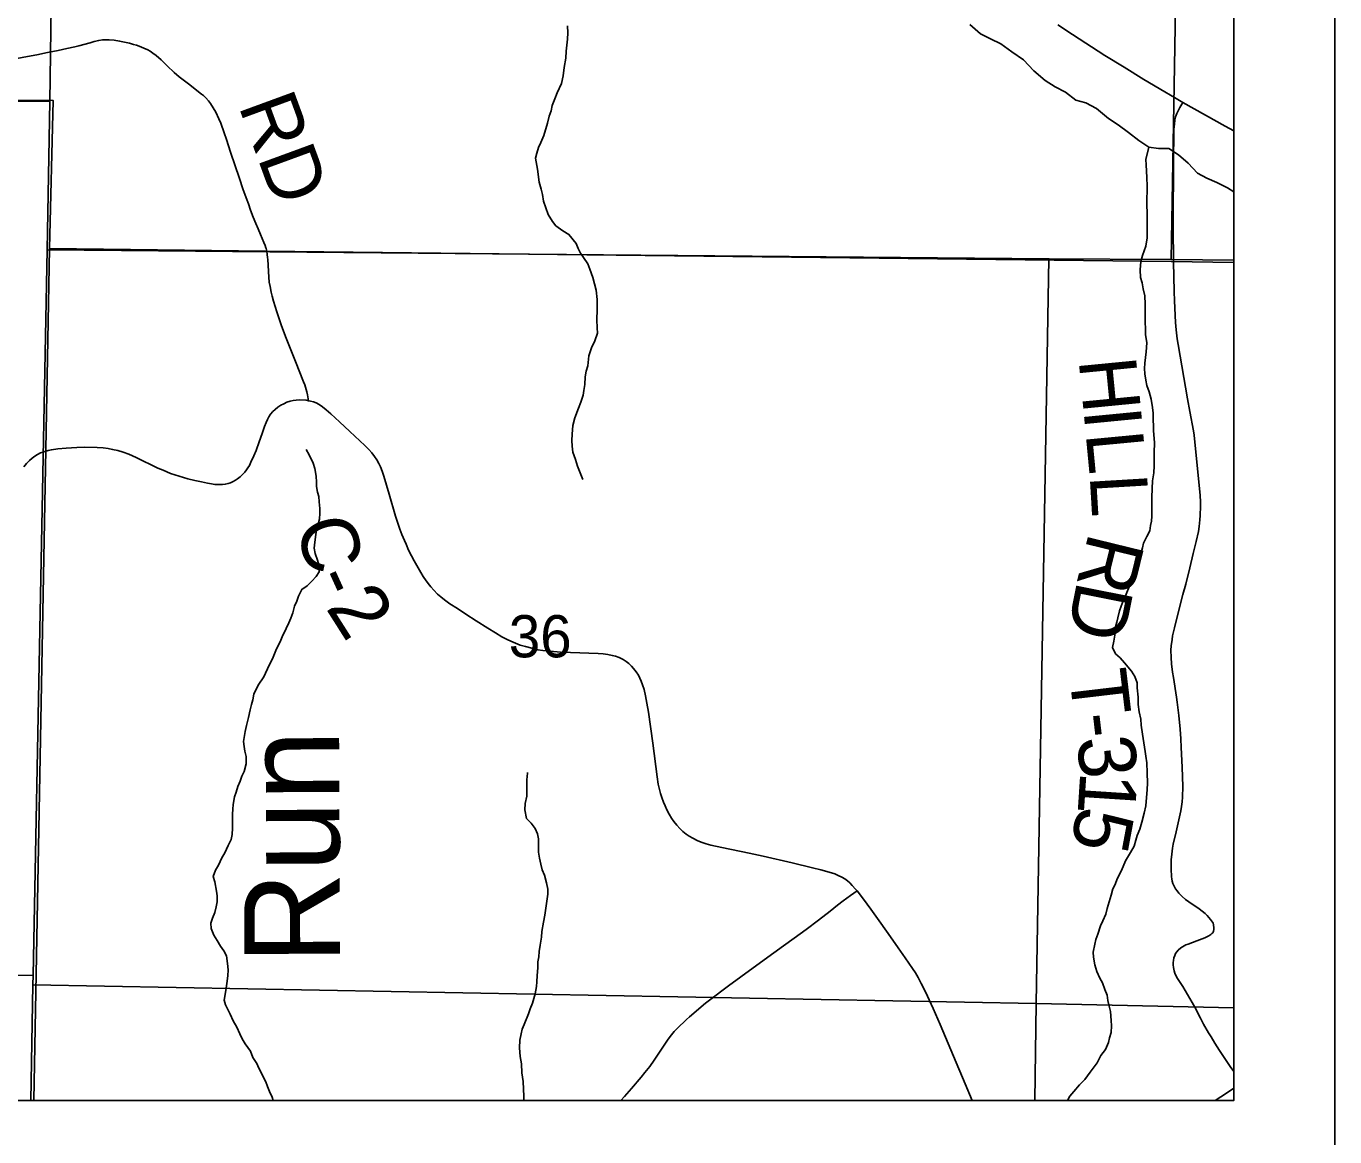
# Model space of a CAD drawing. Extents: x 0 to 34, y 0 to 22.
# Drawn here: x 24.203 to 25.5, y 13.564 to 14.665 of the extents above; entities that cross this region are included whole.
import ezdxf

# ---------------------------------------------------------------- set-up
doc = ezdxf.new("R2010")
doc.units = 0
for name, color, linetype in [('GM_X_Corporation', 7, 'Continuous'), ('GM_X_County_Road', 7, 'Continuous'), ('GM_X_County_Road_Text', 7, 'Continuous'), ('GM_X_Major_River', 7, 'Continuous'), ('GM_X_Minor_River', 7, 'Continuous'), ('GM_X_Minor_River_Text', 7, 'Continuous'), ('GM_X_Section_Text', 7, 'Continuous'), ('GM_X_Township_Road', 7, 'Continuous'), ('GM_X_Township_Road_Text', 7, 'Continuous'), ('GM_X_US_Route', 7, 'Continuous'), ('SH_Data', 7, 'Continuous')]:
    doc.layers.add(name, color=color, linetype=linetype)

msp = doc.modelspace()

# ---------------------------------------------------------------- linework, layer by layer
at = {"layer": 'GM_X_Corporation'}
msp.add_lwpolyline([(20.2208, 16.9558), (20.1987, 15.2691), (20.203, 14.81), (20.2016, 14.6512), (20.2571, 14.6508), (21.1282, 14.6279), (21.314, 14.623), (22.3464, 14.612), (22.9003, 14.6033), (24.2301, 14.5912), (24.2265, 14.4444), (24.4406, 14.442), (25.338, 14.4317), (25.4, 14.4307), (25.4, 19.0068)], dxfattribs=at)
for points in [[(23.2418, 15.623), (24.2407, 15.6067), (24.2392, 15.4615), (24.2269, 14.5903), (23.2254, 14.5998)], [(24.2392, 15.4615), (25.3552, 15.4512), (25.338, 14.4337), (25.2167, 14.4344), (24.2243, 14.4432), (24.2269, 14.5903)], [(25.4, 14.4329), (25.4, 15.4506), (25.3552, 15.4512), (25.338, 14.4337)], [(18.6, 14.6606), (18.6, 13.6), (24.2109, 13.6), (24.2228, 14.2453), (24.2265, 14.4444), (24.2301, 14.5912), (22.9003, 14.6033), (22.3464, 14.612), (21.314, 14.623), (21.1282, 14.6279), (20.2571, 14.6508), (20.2016, 14.6512), (19.8855, 14.6528), (19.4007, 14.6554), (18.9216, 14.6592)], [(23.2254, 14.5998), (24.2269, 14.5903), (24.2243, 14.4432), (24.2104, 13.724), (23.2038, 13.7171)], [(24.2109, 13.6), (25.4, 13.6), (25.4, 14.4307), (25.338, 14.4317), (24.4406, 14.442), (24.2265, 14.4444), (24.2228, 14.2453)], [(24.2243, 14.4432), (25.2167, 14.4344), (25.2042, 13.6962), (24.2101, 13.7145), (24.2104, 13.724)], [(25.4, 13.6919), (25.4, 14.4329), (25.338, 14.4337), (25.2167, 14.4344), (25.2042, 13.6962)], [(23.201, 13.6), (24.208, 13.6), (24.2101, 13.7145), (24.2104, 13.724), (23.2038, 13.7171)], [(24.208, 13.6), (25.2027, 13.6), (25.2042, 13.6962), (24.2101, 13.7145)], [(25.2027, 13.6), (25.4, 13.6), (25.4, 13.6919), (25.2042, 13.6962)]]:
    msp.add_lwpolyline(points, close=True, dxfattribs=at)
at = {"layer": 'GM_X_County_Road'}
for points in [[(24.2198, 14.2427), (24.2218, 14.2434), (24.2252, 14.2443), (24.2285, 14.245), (24.2349, 14.2459), (24.2429, 14.2467), (24.2536, 14.2473), (24.2611, 14.2475), (24.2737, 14.2473), (24.2798, 14.2468), (24.2848, 14.2461), (24.2891, 14.2453), (24.2943, 14.2441), (24.2994, 14.2426), (24.3051, 14.2405), (24.3124, 14.2372), (24.334, 14.2269), (24.339, 14.2246), (24.3465, 14.2216), (24.3507, 14.2201), (24.3637, 14.2163), (24.3704, 14.2146), (24.3772, 14.2131), (24.3832, 14.2119), (24.3872, 14.2112), (24.3904, 14.2107), (24.393, 14.2105), (24.3953, 14.2104), (24.398, 14.2105), (24.4007, 14.2108), (24.4034, 14.2114), (24.4057, 14.2122), (24.4084, 14.2135), (24.4107, 14.2147), (24.4129, 14.2162), (24.4153, 14.2181), (24.4178, 14.2203), (24.4201, 14.2228), (24.4218, 14.2252), (24.4232, 14.2271), (24.4246, 14.2295), (24.4261, 14.2326), (24.429, 14.2389), (24.4313, 14.2441), (24.4344, 14.253), (24.4372, 14.261), (24.4397, 14.2682), (24.4412, 14.2721), (24.4426, 14.2751), (24.444, 14.2776), (24.4456, 14.2801), (24.4477, 14.2828), (24.4502, 14.2849), (24.4528, 14.2871), (24.4557, 14.2891), (24.4586, 14.2906), (24.4618, 14.292), (24.4649, 14.2932), (24.4678, 14.2938), (24.471, 14.2942), (24.4747, 14.2944), (24.4808, 14.294), (24.483, 14.2936), (24.4851, 14.2932), (24.488, 14.2924), (24.4906, 14.2914), (24.4936, 14.2898), (24.497, 14.2876), (24.5008, 14.2847), (24.5054, 14.2806), (24.5139, 14.2726), (24.5242, 14.2631), (24.5389, 14.2491), (24.5428, 14.2452), (24.546, 14.2418), (24.5485, 14.2384), (24.5508, 14.2351), (24.5527, 14.2315), (24.5544, 14.228), (24.5561, 14.2238), (24.5578, 14.2189), (24.5632, 14.2011), (24.5695, 14.1791), (24.5724, 14.1702), (24.5738, 14.1662), (24.5757, 14.161), (24.5781, 14.1551), (24.5798, 14.1513), (24.5823, 14.1456), (24.5851, 14.1399), (24.5879, 14.1349), (24.5917, 14.1279), (24.5946, 14.1232), (24.5969, 14.1195), (24.5998, 14.1151), (24.603, 14.1109), (24.6043, 14.1092), (24.6073, 14.1058), (24.6109, 14.102), (24.6141, 14.0991), (24.6179, 14.0961), (24.6233, 14.0923), (24.6307, 14.0875), (24.639, 14.0821), (24.6494, 14.0753), (24.6607, 14.0682), (24.6684, 14.0634), (24.6748, 14.0597), (24.68, 14.0569), (24.6837, 14.0551), (24.6881, 14.0532), (24.6929, 14.0514), (24.6981, 14.0498), (24.7043, 14.0482), (24.7105, 14.0468), (24.7154, 14.046), (24.7188, 14.0455), (24.7225, 14.0452), (24.7329, 14.0445), (24.7427, 14.0441), (24.7701, 14.043), (24.7751, 14.0426), (24.7798, 14.042), (24.7841, 14.0412), (24.7874, 14.0404), (24.791, 14.039), (24.7948, 14.0372), (24.7978, 14.0352), (24.8006, 14.033), (24.8032, 14.0304), (24.8053, 14.0281), (24.8078, 14.0249), (24.81, 14.0217), (24.8115, 14.0187), (24.8129, 14.0156), (24.8141, 14.012), (24.8156, 14.0072), (24.8171, 14.0011), (24.8184, 13.9938), (24.8199, 13.9848), (24.8244, 13.9541), (24.8286, 13.9207), (24.8297, 13.9135), (24.8309, 13.9081), (24.8319, 13.9043), (24.8331, 13.9004), (24.8349, 13.8956), (24.8365, 13.8919), (24.8383, 13.8881), (24.8406, 13.8838), (24.8429, 13.8798), (24.8452, 13.8765), (24.848, 13.8728), (24.851, 13.8695), (24.854, 13.8667), (24.8573, 13.864), (24.8603, 13.8621), (24.8638, 13.8599), (24.8681, 13.8578), (24.8722, 13.8561), (24.8773, 13.8543), (24.8818, 13.8531), (24.8927, 13.8507), (24.9196, 13.8452), (24.9337, 13.8421), (24.9622, 13.8355), (24.9825, 13.8305), (24.9907, 13.8285), (24.999, 13.8263), (25.0046, 13.8245), (25.008, 13.8231), (25.0116, 13.8214), (25.0144, 13.8198), (25.0173, 13.8176), (25.0194, 13.8157), (25.0219, 13.8131), (25.0252, 13.8093), (25.0266, 13.8076), (25.0331, 13.7996), (25.0402, 13.7895), (25.0469, 13.7802), (25.0574, 13.7655), (25.0674, 13.7513), (25.0744, 13.7415), (25.0817, 13.7307), (25.0844, 13.7264), (25.0873, 13.7217), (25.0902, 13.7158), (25.0943, 13.7076), (25.1019, 13.6911), (25.1089, 13.6753), (25.1221, 13.6439), (25.1338, 13.6163), (25.1408, 13.6)], [(24.2011, 14.2281), (24.2037, 14.2313), (24.2066, 14.2343), (24.2094, 14.2367), (24.2121, 14.2387), (24.2148, 14.2403), (24.2177, 14.2418), (24.2198, 14.2427)], [(24.7927, 13.6), (24.7963, 13.6038), (24.8033, 13.6119), (24.8126, 13.6229), (24.8163, 13.6276), (24.8212, 13.6337), (24.8256, 13.6398), (24.8387, 13.6597), (24.8414, 13.6635), (24.8455, 13.6684), (24.8484, 13.6713), (24.8577, 13.6803), (24.8607, 13.683), (24.8766, 13.6963), (24.8803, 13.6993), (24.8993, 13.7137), (24.9114, 13.7226), (24.9345, 13.7394), (24.9538, 13.7533), (24.9644, 13.761), (24.9761, 13.7695), (24.9884, 13.7787), (24.9999, 13.7876), (25.0071, 13.7934), (25.0128, 13.7978), (25.02, 13.8031), (25.0234, 13.8055), (25.0266, 13.8076)], [(25.3814, 13.6), (25.387, 13.6035), (25.3928, 13.6071), (25.4, 13.6121)]]:
    msp.add_lwpolyline(points, dxfattribs=at)
at = {"layer": 'GM_X_Major_River'}
msp.add_lwpolyline([(25.1385, 14.6664), (25.1488, 14.6574), (25.1587, 14.6522), (25.169, 14.6473), (25.18, 14.6395), (25.1915, 14.6316), (25.2018, 14.6207), (25.2129, 14.6109), (25.2228, 14.6049), (25.2331, 14.5993), (25.2434, 14.5914), (25.2532, 14.5888), (25.2639, 14.5832), (25.2757, 14.5735), (25.2853, 14.5671), (25.2956, 14.5596), (25.3059, 14.5517), (25.3158, 14.545), (25.3253, 14.5435), (25.3355, 14.5436), (25.345, 14.5373), (25.3546, 14.529), (25.3638, 14.5192), (25.3733, 14.5143), (25.3832, 14.5099), (25.3938, 14.5047), (25.4, 14.5008)], dxfattribs=at)
at = {"layer": 'GM_X_Minor_River'}
msp.add_line((24.7, 13.9243), (24.7002, 13.9251), dxfattribs=at)
for points in [[(24.7398, 14.6652), (24.7402, 14.6584), (24.7398, 14.6519), (24.7391, 14.6459), (24.7384, 14.6402), (24.738, 14.6333), (24.7365, 14.6238), (24.7354, 14.6158), (24.7339, 14.6082), (24.7294, 14.5987), (24.7271, 14.593), (24.7245, 14.5862), (24.7237, 14.5808), (24.7215, 14.5755), (24.72, 14.5687), (24.7162, 14.5565), (24.7132, 14.5497), (24.7109, 14.5447), (24.7094, 14.539), (24.7079, 14.5341), (24.7099, 14.5231), (24.7118, 14.5102), (24.7137, 14.5033), (24.7149, 14.498), (24.716, 14.4915), (24.7183, 14.4847), (24.7206, 14.4783), (24.7248, 14.4714), (24.7283, 14.4669), (24.7351, 14.4619), (24.7412, 14.4585), (24.7484, 14.4494), (24.7503, 14.4445), (24.7526, 14.4399), (24.7557, 14.4354), (24.7599, 14.4293), (24.7618, 14.424), (24.7649, 14.4156), (24.7664, 14.4096), (24.7683, 14.4031), (24.7691, 14.394), (24.7691, 14.3841), (24.7688, 14.3739), (24.7692, 14.3659), (24.7696, 14.3606), (24.767, 14.353), (24.7636, 14.3461), (24.7609, 14.3381), (24.7598, 14.3283), (24.7583, 14.3229), (24.7572, 14.3172), (24.7569, 14.3096), (24.7561, 14.3036), (24.7554, 14.299), (24.7531, 14.2921), (24.7505, 14.2861), (24.7471, 14.2766), (24.7452, 14.269), (24.7445, 14.2606)], [(25.3158, 14.545), (25.3128, 14.5326), (25.3132, 14.5273), (25.3136, 14.5147), (25.314, 14.5064), (25.314, 14.5014), (25.3136, 14.4942), (25.3137, 14.4866), (25.3141, 14.4809), (25.3141, 14.4551), (25.3126, 14.4467), (25.3093, 14.4376), (25.3078, 14.4315), (25.307, 14.4232), (25.3074, 14.4156), (25.309, 14.4106), (25.3101, 14.4045), (25.3117, 14.3977), (25.3121, 14.3893), (25.3121, 14.3726), (25.3125, 14.3639), (25.3125, 14.3593), (25.3137, 14.351), (25.313, 14.3422), (25.3119, 14.3308), (25.3115, 14.3255), (25.3119, 14.3202), (25.3127, 14.3141), (25.3138, 14.3088), (25.3161, 14.3024), (25.3181, 14.2951), (25.3192, 14.2868), (25.32, 14.2811), (25.32, 14.2743), (25.3204, 14.2686), (25.3204, 14.2636), (25.3212, 14.2522), (25.3209, 14.242), (25.3209, 14.229), (25.3206, 14.2222), (25.3195, 14.2142), (25.3191, 14.2066), (25.3188, 14.1975), (25.3188, 14.1793), (25.3185, 14.1743), (25.3173, 14.1698), (25.3166, 14.1645), (25.3136, 14.1591), (25.3106, 14.1523), (25.3094, 14.1477), (25.3076, 14.1409), (25.3038, 14.1276), (25.3023, 14.1219), (25.2989, 14.1162), (25.297, 14.1109), (25.2933, 14.1017), (25.2902, 14.0953), (25.2884, 14.09), (25.2865, 14.0854), (25.285, 14.0785), (25.2839, 14.074), (25.2816, 14.066), (25.282, 14.0611), (25.2809, 14.0554), (25.2798, 14.0489), (25.2828, 14.0428), (25.2874, 14.0387), (25.2916, 14.0337), (25.2984, 14.0254), (25.3019, 14.0201), (25.3042, 14.014), (25.3042, 14.0091), (25.305, 13.9996), (25.305, 13.9924), (25.3062, 13.9851), (25.3077, 13.9779), (25.3081, 13.9719), (25.3093, 13.9631), (25.3101, 13.9586), (25.312, 13.946), (25.3128, 13.9411), (25.3139, 13.9346), (25.314, 13.9248), (25.3144, 13.9145), (25.314, 13.9081), (25.3129, 13.8921), (25.3111, 13.8849), (25.3088, 13.8758), (25.3069, 13.8689), (25.3043, 13.8625), (25.3028, 13.8579), (25.3013, 13.8522), (25.2975, 13.8457), (25.2926, 13.8374), (25.2885, 13.8279), (25.2843, 13.8195), (25.2824, 13.8142), (25.2802, 13.8096), (25.2783, 13.8035), (25.2745, 13.7902), (25.2731, 13.7845)], [(24.7445, 14.2606), (24.7441, 14.2541), (24.7445, 14.2484), (24.7449, 14.2427), (24.7476, 14.2352), (24.7495, 14.2287), (24.7518, 14.2238), (24.7548, 14.2154)], [(24.4922, 14.2031), (24.491, 14.2084), (24.491, 14.213), (24.4906, 14.2187), (24.4894, 14.2263), (24.4879, 14.2316), (24.4837, 14.2399), (24.4807, 14.2453)], [(24.4482, 13.6), (24.4471, 13.6033), (24.4445, 13.609), (24.4425, 13.6139), (24.441, 13.6185), (24.4341, 13.6321), (24.4318, 13.6367), (24.428, 13.6427), (24.4257, 13.6488), (24.4204, 13.656), (24.4173, 13.6609), (24.415, 13.6659), (24.412, 13.6727), (24.4085, 13.6788), (24.4055, 13.6856), (24.4009, 13.6947), (24.3997, 13.6993), (24.4012, 13.7091), (24.4023, 13.716), (24.4031, 13.7236), (24.4034, 13.7293), (24.403, 13.7357), (24.4018, 13.7433), (24.3992, 13.7483), (24.3961, 13.7528), (24.3927, 13.7585), (24.3892, 13.7638), (24.3866, 13.7703), (24.3865, 13.7756), (24.3881, 13.7805), (24.3903, 13.7862), (24.3918, 13.7919), (24.3926, 13.7969), (24.3925, 13.8029), (24.3921, 13.8075), (24.3902, 13.8166), (24.3887, 13.8219), (24.3909, 13.8284), (24.3939, 13.8333), (24.3973, 13.8406), (24.4004, 13.8455), (24.4034, 13.8527), (24.4064, 13.8588), (24.4075, 13.8637), (24.4079, 13.8698), (24.4078, 13.8839), (24.4082, 13.8888), (24.4085, 13.8934), (24.4097, 13.901), (24.4115, 13.9055), (24.413, 13.9112), (24.4153, 13.9166), (24.4172, 13.9215), (24.4194, 13.9261), (24.4213, 13.9337), (24.4213, 13.9409), (24.4201, 13.9462), (24.4194, 13.9507), (24.4186, 13.9557), (24.4205, 13.9656), (24.4216, 13.9716), (24.4238, 13.9796), (24.4253, 13.9872), (24.4268, 13.9925), (24.4279, 13.9971), (24.4291, 14.0028), (24.4332, 14.0115), (24.4389, 14.0199), (24.4442, 14.0313), (24.4475, 14.0378), (24.4513, 14.0477), (24.4551, 14.0545), (24.457, 14.0595), (24.4611, 14.0678), (24.4638, 14.0735), (24.4656, 14.0781), (24.4675, 14.0834), (24.4694, 14.0899), (24.4717, 14.0948), (24.4732, 14.0998), (24.4766, 14.1066), (24.4819, 14.11), (24.4864, 14.1146), (24.4906, 14.1195), (24.4936, 14.1241), (24.4939, 14.129), (24.492, 14.1355), (24.4897, 14.142), (24.4889, 14.1473), (24.4893, 14.1533), (24.4904, 14.1609), (24.4912, 14.1655), (24.4927, 14.1712), (24.4942, 14.1761), (24.4945, 14.1822), (24.4945, 14.1868), (24.4937, 14.1932), (24.4933, 14.1986), (24.4922, 14.2031)], [(24.6966, 13.6), (24.6966, 13.6041), (24.6962, 13.611), (24.6958, 13.6186), (24.6946, 13.6273), (24.6942, 13.6364), (24.693, 13.6436), (24.6922, 13.652), (24.6926, 13.6596), (24.6937, 13.666), (24.6948, 13.6706), (24.6967, 13.6752), (24.7012, 13.6858), (24.7027, 13.6908), (24.705, 13.6965), (24.7065, 13.701), (24.7076, 13.7056), (24.7091, 13.7128), (24.7095, 13.7174), (24.7098, 13.7238), (24.7102, 13.7314), (24.7105, 13.7375), (24.7113, 13.7424), (24.7116, 13.7477), (24.7128, 13.7538), (24.7139, 13.7618), (24.7142, 13.7675), (24.7161, 13.7766), (24.7172, 13.7835), (24.7183, 13.7907), (24.7194, 13.7975), (24.7202, 13.8043), (24.7202, 13.8093), (24.719, 13.8157), (24.7171, 13.8233), (24.7148, 13.8286), (24.7132, 13.8343), (24.7121, 13.84), (24.7109, 13.8461), (24.7109, 13.8594), (24.7101, 13.8643), (24.7078, 13.8697), (24.7036, 13.875), (24.699, 13.8795), (24.6975, 13.8879), (24.6979, 13.8943), (24.6993, 13.9015), (24.6993, 13.9179), (24.7, 13.9243)], [(25.2731, 13.7845), (25.27, 13.7781), (25.2678, 13.7731), (25.2651, 13.7648), (25.2633, 13.7595), (25.2621, 13.7549), (25.2606, 13.7469), (25.261, 13.742), (25.2622, 13.7344), (25.2641, 13.7279), (25.2672, 13.7211), (25.2699, 13.7165), (25.2722, 13.7101), (25.2745, 13.7044), (25.2752, 13.6991), (25.2764, 13.6934), (25.2776, 13.6881), (25.2783, 13.6793), (25.2787, 13.674), (25.2784, 13.6672), (25.2769, 13.6622), (25.2758, 13.6573), (25.2727, 13.6505), (25.2682, 13.6444), (25.2644, 13.6372), (25.2576, 13.628), (25.2523, 13.6208), (25.247, 13.6155), (25.2414, 13.609), (25.2376, 13.6041), (25.2351, 13.6)]]:
    msp.add_lwpolyline(points, dxfattribs=at)
at = {"layer": 'GM_X_Township_Road'}
msp.add_line((25.3401, 14.4313), (25.3401, 14.4352), dxfattribs=at)
for points in [[(24.4411, 14.4444), (24.4409, 14.4452), (24.4401, 14.4473), (24.4389, 14.4505), (24.4357, 14.4583), (24.4334, 14.4639), (24.4311, 14.4693), (24.4284, 14.4757), (24.4257, 14.4826), (24.4237, 14.4886), (24.4214, 14.4947), (24.4182, 14.5035), (24.4147, 14.5139), (24.406, 14.5399), (24.4019, 14.5526), (24.3996, 14.5593), (24.3962, 14.5686), (24.3944, 14.573), (24.3912, 14.5796), (24.3888, 14.584), (24.386, 14.5882), (24.384, 14.5909), (24.3813, 14.594), (24.3791, 14.596), (24.3772, 14.5976), (24.3644, 14.6076), (24.3549, 14.6147), (24.3501, 14.6189), (24.343, 14.6257), (24.3371, 14.6315), (24.3322, 14.6357), (24.329, 14.6382), (24.3263, 14.64), (24.3238, 14.6414), (24.3201, 14.6431), (24.3155, 14.6449), (24.3128, 14.6459), (24.3099, 14.6468), (24.3058, 14.6479), (24.2959, 14.6501), (24.2906, 14.651), (24.2858, 14.6514), (24.2789, 14.6512), (24.2754, 14.6507), (24.2707, 14.6496), (24.2667, 14.6485), (24.2555, 14.6455), (24.2516, 14.6444), (24.2437, 14.6427), (24.2351, 14.6408), (24.2247, 14.6388), (24.2139, 14.6366), (24.2047, 14.6348), (24.1836, 14.6309)], [(25.3401, 14.4352), (25.3399, 14.462), (25.3402, 14.5386), (25.3404, 14.5523), (25.3406, 14.5623), (25.341, 14.5678), (25.3416, 14.5721), (25.3423, 14.5751), (25.3435, 14.5783), (25.3465, 14.5843), (25.3495, 14.5892)], [(24.483, 14.2936), (24.4823, 14.2993), (24.4816, 14.3023), (24.4794, 14.3092), (24.4782, 14.3123), (24.4704, 14.3324), (24.4658, 14.3439), (24.4603, 14.3574), (24.4561, 14.3688), (24.4534, 14.3767), (24.4518, 14.3816), (24.4485, 14.3922), (24.447, 14.3972), (24.4461, 14.4012), (24.445, 14.4068), (24.4442, 14.4111), (24.4437, 14.416), (24.4428, 14.4335), (24.4426, 14.4357), (24.4423, 14.4385), (24.4417, 14.4419), (24.4411, 14.4444)], [(25.4, 13.6287), (25.3963, 13.6336), (25.3929, 13.6385), (25.3857, 13.6495), (25.3811, 13.6568), (25.3774, 13.6629), (25.3749, 13.667), (25.37, 13.6757), (25.367, 13.6814), (25.3612, 13.6924), (25.3586, 13.6972), (25.3493, 13.7128), (25.3441, 13.721), (25.3426, 13.7237), (25.3415, 13.7261), (25.3407, 13.7285), (25.3401, 13.7316), (25.3399, 13.7343), (25.3398, 13.7367), (25.34, 13.7386), (25.3405, 13.7415), (25.3414, 13.7438), (25.3423, 13.7455), (25.3434, 13.7472), (25.3447, 13.7488), (25.3473, 13.7512), (25.3506, 13.7532), (25.3525, 13.7541), (25.3546, 13.755), (25.3633, 13.7581), (25.3711, 13.7613), (25.3752, 13.7633), (25.377, 13.7644), (25.3783, 13.7654), (25.379, 13.7661), (25.3795, 13.7668), (25.3797, 13.7678), (25.38, 13.7694), (25.3801, 13.7708), (25.3798, 13.7745), (25.3795, 13.7756), (25.3788, 13.7767), (25.3768, 13.7794), (25.3735, 13.7832), (25.3714, 13.7852), (25.3655, 13.7898), (25.3622, 13.7921), (25.3587, 13.7947), (25.3554, 13.7969), (25.352, 13.7993), (25.3487, 13.8021), (25.3456, 13.8054), (25.3437, 13.8077), (25.3422, 13.8099), (25.3407, 13.8124), (25.3396, 13.8151), (25.339, 13.8174), (25.3385, 13.8197), (25.3383, 13.8218), (25.3379, 13.8296), (25.3378, 13.8327), (25.338, 13.8387), (25.3382, 13.8412), (25.3392, 13.85), (25.3399, 13.854), (25.3427, 13.8662), (25.3462, 13.8812), (25.3474, 13.8869), (25.3481, 13.8912), (25.3487, 13.8961), (25.3491, 13.9007), (25.3494, 13.9113), (25.3488, 13.9303), (25.3479, 13.95), (25.3473, 13.9585), (25.3467, 13.968), (25.3453, 13.9814), (25.3438, 13.9947), (25.3431, 13.9997), (25.3402, 14.0192), (25.3393, 14.0246), (25.3383, 14.0328), (25.3378, 14.0391), (25.3375, 14.0463), (25.3377, 14.0505), (25.3387, 14.057), (25.3393, 14.0606), (25.3412, 14.0685), (25.3452, 14.0847), (25.3495, 14.1015), (25.3523, 14.1118), (25.3563, 14.1278), (25.3597, 14.1423), (25.3627, 14.1539), (25.3649, 14.1639), (25.3656, 14.169), (25.3663, 14.1754), (25.3667, 14.1798), (25.367, 14.1892), (25.3669, 14.1929), (25.3666, 14.2), (25.3647, 14.2196), (25.3605, 14.2595), (25.3599, 14.2637), (25.3565, 14.2828), (25.3541, 14.2954), (25.3447, 14.3493), (25.3438, 14.3548), (25.3428, 14.364), (25.3422, 14.3711), (25.341, 14.3925), (25.3408, 14.4019), (25.3401, 14.4313)]]:
    msp.add_lwpolyline(points, dxfattribs=at)
at = {"layer": 'GM_X_US_Route'}
msp.add_lwpolyline([(25.2255, 14.6662), (25.24, 14.6567), (25.2721, 14.6359), (25.2914, 14.6241), (25.3109, 14.6121), (25.3316, 14.5997), (25.3429, 14.5931), (25.3495, 14.5892), (25.3719, 14.5767), (25.3915, 14.5659), (25.4, 14.5612)], dxfattribs=at)
at = {"layer": 'SH_Data'}
for points in [[(18.5, 20.5), (25.5, 20.5), (25.5, 13.5), (18.5, 13.5)], [(18.6, 20.4), (25.4, 20.4), (25.4, 13.6), (18.6, 13.6)]]:
    msp.add_lwpolyline(points, close=True, dxfattribs=at)

# ---------------------------------------------------------------- texts
at = {"layer": 'GM_X_County_Road_Text'}
for s, rotation, p in [('C', 286.088, (24.4697, 14.1706)), ('-', 294.4045, (24.4858, 14.1173)), ('2', 302.4301, (24.4996, 14.0884))]:
    msp.add_text(s, height=0.0568, rotation=rotation, dxfattribs=at).set_placement(p)
at = {"layer": 'GM_X_Minor_River_Text'}
msp.add_text('Run', height=0.0947, rotation=90.2017, dxfattribs=at).set_placement((24.5143, 13.7351))
at = {"layer": 'GM_X_Section_Text'}
msp.add_text('36', height=0.04186, rotation=0, dxfattribs=at).set_placement((24.6816, 14.0392))
at = {"layer": 'GM_X_Township_Road_Text'}
for s, height, rotation, p in [('RD', 0.05682, 290.1536, (24.4134, 14.5862)), ('H', 0.0568, 275.5638, (25.2461, 14.3342)), ('I', 0.0568, 275.5351, (25.2509, 14.2845)), ('L', 0.0568, 275.4121, (25.2531, 14.2613)), ('L', 0.0568, 273.4349, (25.2571, 14.2195)), ('R', 0.0568, 256.243, (25.2567, 14.1644)), ('D', 0.0568, 258.7843, (25.245, 14.1164)), ('T', 0.0568, 276.7482, (25.2365, 14.0241)), ('-', 0.0568, 276.6574, (25.2415, 13.982)), ('3', 0.0568, 276.1523, (25.2442, 13.9589)), ('1', 0.0568, 266.2766, (25.2479, 13.9267)), ('5', 0.0568, 259.4382, (25.2459, 13.8935))]:
    msp.add_text(s, height=height, rotation=rotation, dxfattribs=at).set_placement(p)

doc.saveas('drawing.dxf')
